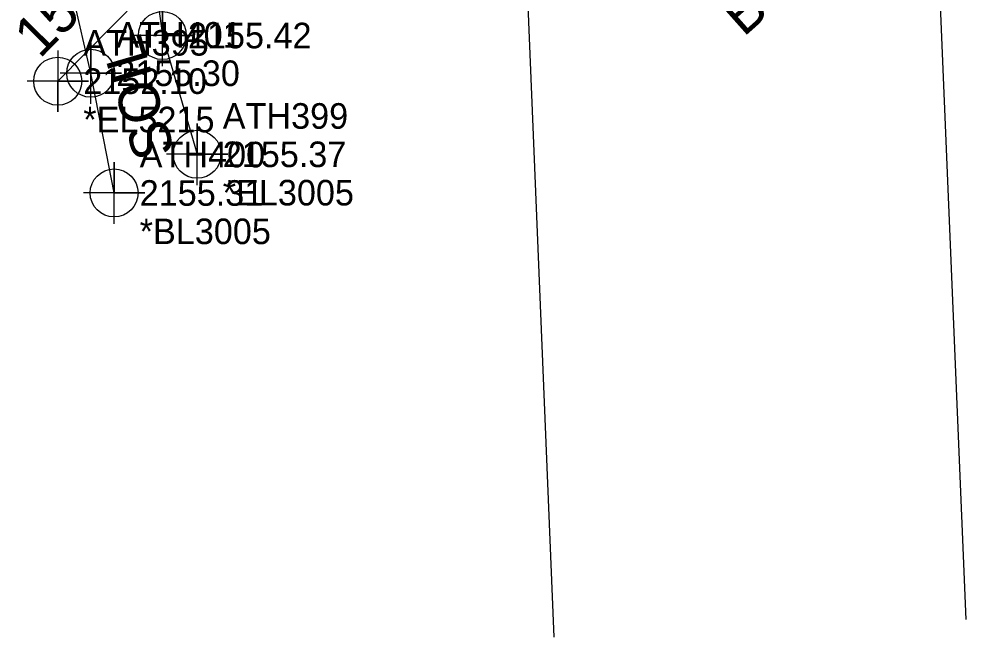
# Model space of a CAD drawing. Extents: x 890923 to 892150, y 696020 to 698102.
# Drawn here: x 891559.7 to 891652.3, y 696306.1 to 696366.5 of the extents above; entities that cross this region are included whole.
import ezdxf

# ---------------------------------------------------------------- set-up
doc = ezdxf.new("R2010")
doc.units = 0
for name, color, linetype in [('Exist Building', 7, 'Continuous'), ('Exist Building Text', 7, 'Continuous'), ('Exist Roads Soil', 7, 'Continuous'), ('Exist Roads Soil Cogo Comment', 7, 'Continuous'), ('Exist Roads Soil Cogo Elevation', 7, 'Continuous'), ('Exist Roads Soil Cogo Number', 7, 'Continuous'), ('Exist Roads Soil Cogo Point CELL', 7, 'Continuous'), ('Exist Roads Soil Text', 7, 'Continuous'), ('Exist Structure Minor Pipes CMP 15 Inch', 7, 'Continuous'), ('Exist Structure Minor Pipes CMP 15 Inch Cogo Comment', 7, 'Continuous'), ('Exist Structure Minor Pipes CMP 15 Inch Cogo Elevation', 7, 'Continuous'), ('Exist Structure Minor Pipes CMP 15 Inch Cogo Number', 7, 'Continuous'), ('Exist Structure Minor Pipes CMP 15 Inch Cogo Point CELL', 7, 'Continuous'), ('Exist Structure Minor Pipes CMP 15 Inch Text', 7, 'Continuous')]:
    doc.layers.add(name, color=color, linetype=linetype)

msp = doc.modelspace()

# ---------------------------------------------------------------- linework, layer by layer
at = {"layer": 'Exist Building'}
for p, q in [((891652.318, 696307.783), (891649.073, 696385.664)), ((891612.065, 696306.083), (891608.819, 696383.987))]:
    msp.add_line(p, q, dxfattribs=at)
at = {"layer": 'Exist Roads Soil'}
for points in [[(891576.823, 696391.217), (891571.807, 696379.036), (891573.744, 696364.875), (891577.147, 696353.266)], [(891569.027, 696349.487), (891566.74, 696361.191), (891563.314, 696376.211)]]:
    msp.add_lwpolyline(points, dxfattribs=at)
at = {"layer": 'Exist Roads Soil Cogo Point CELL'}
for points in [[(891573.744, 696361.875), (891573.744, 696367.875), (891573.744, 696364.875), (891576.744, 696364.875), (891570.744, 696364.875)], [(891566.74, 696358.191), (891566.74, 696364.191), (891566.74, 696361.191), (891569.74, 696361.191), (891563.74, 696361.191)], [(891577.147, 696350.266), (891577.147, 696356.266), (891577.147, 696353.266), (891580.147, 696353.266), (891574.147, 696353.266)], [(891569.027, 696346.487), (891569.027, 696352.487), (891569.027, 696349.487), (891572.027, 696349.487), (891566.027, 696349.487)]]:
    msp.add_lwpolyline(points, dxfattribs=at)
for centre in [(891573.744, 696364.875), (891566.74, 696361.191), (891577.147, 696353.266), (891569.027, 696349.487)]:
    msp.add_circle(centre, 2.344, dxfattribs=at)
at = {"layer": 'Exist Structure Minor Pipes CMP 15 Inch'}
msp.add_line((891575.019, 696372.063), (891563.515, 696360.414), dxfattribs=at)
at = {"layer": 'Exist Structure Minor Pipes CMP 15 Inch Cogo Point CELL'}
msp.add_lwpolyline([(891563.515, 696363.414), (891563.515, 696357.414), (891563.515, 696360.414), (891566.515, 696360.414), (891560.515, 696360.414)], dxfattribs=at)
msp.add_circle((891563.515, 696360.414), 2.344, dxfattribs=at)

# ---------------------------------------------------------------- texts
at = {"layer": 'Exist Building Text'}
msp.add_text('B', height=4, rotation=41.6491, dxfattribs=at).set_placement((891630.56, 696364.668))
at = {"layer": 'Exist Roads Soil Cogo Comment'}
for s, p in [('*EL3005', (891579.647, 696348.266)), ('*BL3005', (891571.527, 696344.487))]:
    msp.add_text(s, height=2.5, dxfattribs=at).set_placement(p)
at = {"layer": 'Exist Roads Soil Cogo Elevation'}
for s, p in [('2155.42', (891576.244, 696363.625)), ('2155.30', (891569.24, 696359.941)), ('2155.37', (891579.647, 696352.016)), ('2155.31', (891571.527, 696348.237))]:
    msp.add_text(s, height=2.5, dxfattribs=at).set_placement(p)
at = {"layer": 'Exist Roads Soil Cogo Number'}
for s, p in [('ATH401', (891569.24, 696363.691)), ('ATH399', (891579.647, 696355.766)), ('ATH400', (891571.527, 696351.987))]:
    msp.add_text(s, height=2.5, dxfattribs=at).set_placement(p)
at = {"layer": 'Exist Roads Soil Text'}
msp.add_text('SOIL', height=4, rotation=106.33769, dxfattribs=at).set_placement((891574.997, 696353.49))
at = {"layer": 'Exist Structure Minor Pipes CMP 15 Inch Cogo Comment'}
msp.add_text('*EL5215', height=2.5, dxfattribs=at).set_placement((891566.015, 696355.414))
at = {"layer": 'Exist Structure Minor Pipes CMP 15 Inch Cogo Elevation'}
msp.add_text('2152.10', height=2.5, dxfattribs=at).set_placement((891566.015, 696359.164))
at = {"layer": 'Exist Structure Minor Pipes CMP 15 Inch Cogo Number'}
msp.add_text('ATH395', height=2.5, dxfattribs=at).set_placement((891566.015, 696362.914))
at = {"layer": 'Exist Structure Minor Pipes CMP 15 Inch Text'}
msp.add_text('15" CMP', height=4, rotation=45.35882, dxfattribs=at).set_placement((891561.746, 696362.537))

doc.saveas('drawing.dxf')
